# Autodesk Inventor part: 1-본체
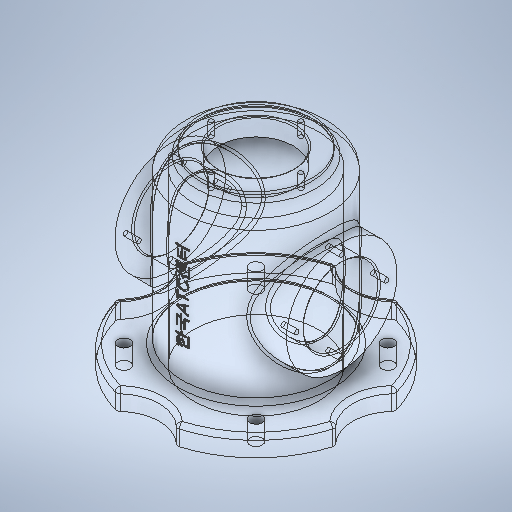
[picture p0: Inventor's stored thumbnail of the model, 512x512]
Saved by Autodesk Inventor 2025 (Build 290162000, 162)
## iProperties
Created: 2026-07
Part Number: 1-본체
Material: 일반
Document SubType Name: Modeling
Designer: KDI
Density: 1 g/cm^3
Appearance: 기본값
Author: KDI
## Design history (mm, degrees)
sketch "스케치1" dims "d0" = 164
  geometry: L1 (0, 0)-(0, -82); L2 (0, 0)-(-47.73, -47.73); L3 (0, 0)-(-67.5, 0); C1 r 30 at (100, 0); C2 r 30 at (0, 100); C3 r 30 at (-100, 0); C4 r 30 at (0, -100); C5 r 4.5 at (-47.73, -47.73); C6 r 4.5 at (-47.73, 47.73); C7 r 4.5 at (47.73, -47.73); C8 r 4.5 at (47.73, 47.73); A1 r 67.5 centre (0, 0) between (-47.73, -47.73) and (-67.5, 0); 10 further points
  constraints: 9 centre point, 6 end point, 3 coincident, 3 symmetric about line, 2 point on circle, 1 horizontal, 1 horizontal alignment, 1 vertical, 15 other
  dimensions: "d1" = 60 diameter of C1; "d2" = 100 distance of point (0, 0) C1.centre; "d5" = 360 deg dimension on point (0, 0) C1.centre (derived); "d7" = 135 diameter of A1; "d8" = 45 deg angle of L1 L2; "d9" = 9 diameter of C5
extrude "돌출1" new body sketch "스케치1" distance "d10" = 14; taper "d11" = 0 deg
sketch "스케치2"
  geometry: C1 r 53 at (0, 0); 1 further point
  constraints: 1 centre point, 1 coincident
  dimensions: "d12" = 106 diameter of C1
extrude "돌출2" join sketch "스케치2" distance "d13" = 132; taper "d14" = 0 deg
sketch "스케치3"
  geometry: C1 r 53 at (0, 0) reference; C2 r 40 at (0, 0); 1 further point
  constraints: 1 centre point, 1 coincident
  dimensions: "d15" = 80 diameter of C2
extrude "돌출3" join sketch "스케치3" distance "d16" = 5; taper "d17" = 0 deg
sketch "스케치4"
  geometry: C1 r 40 at (68, 0); 1 further point
  constraints: 1 centre point, 1 horizontal alignment
  dimensions: "d18" = 80 diameter of C1; "d19" = 68 distance of point (0, 0) C1.centre
extrude "돌출4" join sketch "스케치4" stored distance "d20" = 124; taper "d21" = 0 deg
sketch "스케치5"
  geometry: C1 r 45 at (0, 0); 1 further point
  constraints: 1 centre point, 1 coincident
  dimensions: "d22" = 90 diameter of C1
extrude "돌출5" cut sketch "스케치5" distance "d23" = 124; taper "d24" = 0 deg
sketch "스케치6"
  geometry: C1 r 27 at (0, 0); 1 further point
  constraints: 1 centre point, 1 coincident
  dimensions: "d25" = 54 diameter of C1
extrude "돌출6" cut sketch "스케치6" distance "d26" = 124; taper "d27" = 0 deg
sketch "스케치7"
  geometry: A1 r 32.5 centre (0, 0) between (0, 32.5) and (-32.5, 0); 3 further points
  constraints: 4 point on circle, 2 horizontal alignment, 2 vertical alignment, 1 centre point, 1 coincident
  dimensions: "d28" = 65 diameter of A1
hole "구멍1" sketch "스케치7" at (0, 32.5), (-32.5, 0), (0, -32.5), (32.5, 0) diameter "d29" = 3.242; stored, may be unused: countersink angle "d33" = 90 deg, drill point angle "d35" = 118 deg; dims "d30" = 8, "d31" = 4, "d32" = 2, "d34" = 10
sketch "스케치8"
  geometry: L1 (-21.541, -68)-(21.541, -68) reference; C1 r 27 at (0, 0); 2 further points
  constraints: 1 centre point, 1 midpoint, 1 vertical alignment
  dimensions: "d36" = 54 diameter of C1; "d37" = 68 distance from line of L1 C1.centre
extrude "돌출7" cut sketch "스케치8" extent not by distance; stored distance "d38" = 0; taper "d39" = 0 deg
sketch "스케치9"
  geometry: L1 (-21.541, -68)-(21.541, -68) reference; A1 r 32.5 centre (0, 0) between (0, 32.5) and (-32.5, 0); 5 further points
  constraints: 4 point on circle, 3 vertical alignment, 2 horizontal alignment, 2 midpoint, 1 centre point
  dimensions: "d40" = 65 diameter of A1; "d41" = 68 distance of point (0, -68) A1.centre
hole "구멍2" sketch "스케치9" at (0, 32.5), (-32.5, 0), (0, -32.5), (32.5, 0) diameter "d42" = 3.242; stored, may be unused: countersink angle "d46" = 90 deg, drill point angle "d48" = 118 deg; dims "d43" = 8, "d44" = 4, "d45" = 2, "d47" = 10
sketch "스케치10"
  geometry: L1 (-21.541, 0)-(21.541, 0) reference; 4 further points
  constraints: 2 midpoint, 1 vertical alignment, 1 other
  dimensions: "d49" = 70 distance of point (0, 0) point (0, 70)
feature "엠보싱1" sketch "스케치10" dims "d50" = 0.5, "d51" = 0
fillet "모깎기1" dims "d52" = 10
fillet "모깎기2" dims "d53" = 3
fillet "모깎기3" dims "d54" = 3
fillet "모깎기4" dims "d55" = 3
chamfer "모따기1" distance "d56" = 1; stored, may be unused: second distance "d57" = 2, angle "d58" = 45 deg
node "솔리드1"
mirror "미러1"
node "스케치 - 원형 패턴1" dims "d5" = 360 deg (derived)
feature "A9D066F2-1C7D-4E18-AEED-F7BC21143FA4" dims "d42" = 3.242, "d43" = 8, "d44" = 4, "d45" = 2, "d46" = 90 deg, "d47" = 10, "d48" = 118 deg
